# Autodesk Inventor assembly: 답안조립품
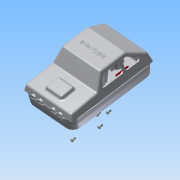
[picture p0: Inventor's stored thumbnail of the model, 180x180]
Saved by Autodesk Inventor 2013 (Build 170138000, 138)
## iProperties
Created: 2015-05
Part Number: 답안조립품
Document SubType Name: Assembly
Designer: Administrator
Author: Administrator
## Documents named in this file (7)
- C:\Documents and Settings\Administrator\바탕 화면\450507V1020\답안조립품.iam
- C:\Documents and Settings\Administrator\바탕 화면\450507V1020\1-본체.ipt
- C:\Documents and Settings\Administrator\바탕 화면\450507V1020\커버.ipt
- C:\Documents and Settings\Administrator\바탕 화면\450507V1020\바퀴.ipt
- C:\Documents and Settings\Administrator\바탕 화면\450507V1020\바퀴고정부.ipt
- C:\Documents and Settings\Administrator\바탕 화면\450507V1020\M4x10.ipt
- C:\Documents and Settings\Administrator\바탕 화면\450507V1020\M2x4.ipt
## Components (9 placed, 3 different names)
1. 1-본체:1
2. M4x10:1
3. M4x10:2
4. M4x10:3
5. M4x10:4
6. M2x4:1
7. M2x4:2
8. M2x4:3
9. M2x4:4
